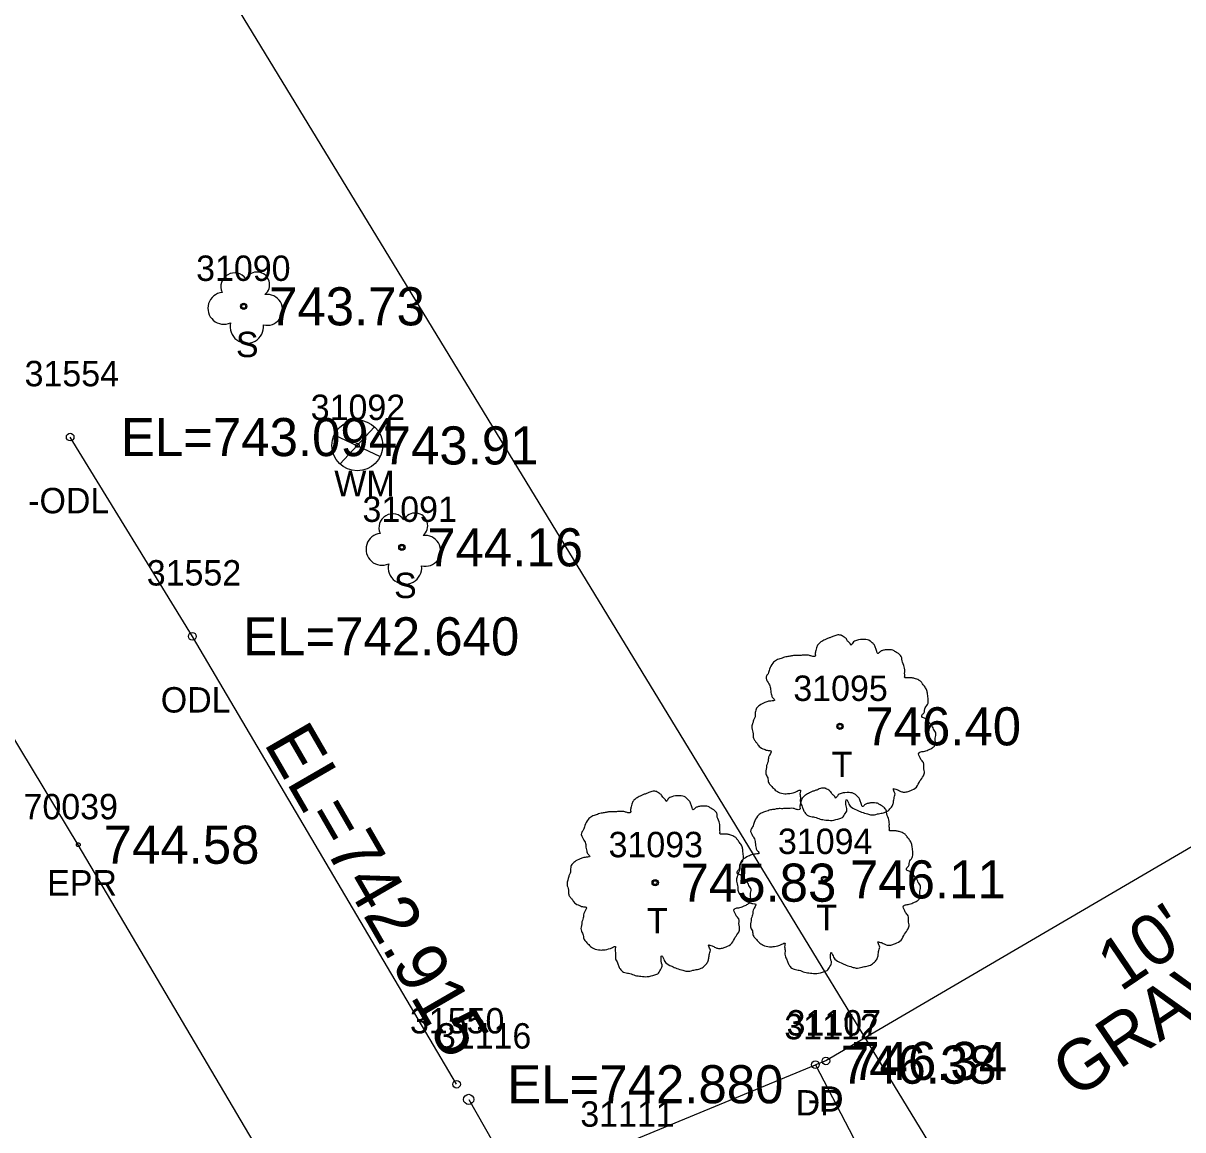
# Model space of a CAD drawing. Extents: x 1375131 to 1378678, y 999028 to 1004053.
# Drawn here: x 1377868.14 to 1377913.81, y 1000838.71 to 1000882.28 of the extents above; entities that cross this region are included whole.
import ezdxf

# ---------------------------------------------------------------- set-up
doc = ezdxf.new("R2010")
doc.units = 0
for name, color, linetype in [('RD_EX_DR_Pipe', 7, 'Continuous'), ('RD_EX_DR_Pipe_txCode', 7, 'Continuous'), ('RD_EX_Driveway', 7, 'Continuous'), ('RD_EX_Driveway_txCode', 7, 'Continuous'), ('RD_EX_H2O', 7, 'Continuous'), ('RD_EX_H2O_txCode', 7, 'Continuous'), ('RD_EX_Road', 7, 'Continuous'), ('RD_EX_Road_txCode', 7, 'Continuous'), ('RD_EX_RW', 7, 'Continuous'), ('RD_EX_TX_Driveway_ELEV', 7, 'Continuous'), ('RD_EX_TX_H2O_ELEV', 7, 'Continuous'), ('RD_EX_TX_Road_ELEV', 7, 'Continuous'), ('RD_EX_TX_UT_ELEV', 7, 'Continuous'), ('RD_EX_TX_VEG_ELEV', 7, 'Continuous'), ('RD_EX_UT', 7, 'Continuous'), ('RD_EX_UT_txCode', 7, 'Continuous'), ('RD_EX_VEG', 7, 'Continuous'), ('RD_EX_VEG_txCode', 7, 'Continuous'), ('RD_SMD_Locator', 7, 'Continuous'), ('RD_TX_Misc2', 7, 'Continuous'), ('RD_TX_Pipe_ElevEX', 7, 'Continuous')]:
    doc.layers.add(name, color=color, linetype=linetype)

msp = doc.modelspace()

# ---------------------------------------------------------------- linework, layer by layer
at = {"layer": 'RD_EX_DR_Pipe'}
msp.add_line((1377885.684, 1000839.91), (1377895.89, 1000822.121), dxfattribs=at)
at = {"layer": 'RD_EX_Driveway'}
for points in [[(1377966.861, 1000881.398), (1377933.173, 1000860.964), (1377899.756, 1000841.424), (1377899.343, 1000841.276)], [(1377878.223, 1000836.536), (1377891.027, 1000837.833), (1377899.343, 1000841.276), (1377903.835, 1000832.654), (1377898.158, 1000826.934), (1377890.381, 1000815.954)]]:
    msp.add_lwpolyline(points, dxfattribs=at)
at = {"layer": 'RD_EX_H2O'}
msp.add_lwpolyline([(1377885.206, 1000840.506), (1377874.8, 1000858.139), (1377869.987, 1000865.983)], dxfattribs=at)
at = {"layer": 'RD_EX_Road'}
msp.add_lwpolyline([(1377899.668, 1000800.294), (1377898.717, 1000801.843), (1377870.308, 1000849.935), (1377847.281, 1000887.888), (1377815.153, 1000940.575), (1377781.512, 1000995.259), (1377748.623, 1001049.208), (1377716.579, 1001099.532), (1377686.671, 1001148.78), (1377656.469, 1001199.107), (1377629.542, 1001244.184), (1377599.886, 1001292.672), (1377570.873, 1001341.428), (1377539.828, 1001392.468), (1377511.01, 1001440.306), (1377480.717, 1001489.998), (1377449.725, 1001541.494), (1377420.899, 1001591.946), (1377390.45, 1001644.414)], dxfattribs=at)
at = {"layer": 'RD_EX_RW'}
msp.add_line((1377592.75, 1001348.439), (1377983.574, 1000707.362), dxfattribs=at)
at = {"layer": 'RD_EX_UT'}
for p, q in [((1377880.622, 1000864.926), (1377881.956, 1000866.374)), ((1377880.381, 1000866.074), (1377882.197, 1000865.217))]:
    msp.add_line(p, q, dxfattribs=at)
msp.add_circle((1377881.298, 1000865.655), 1, dxfattribs=at)
at = {"layer": 'RD_EX_VEG'}
for centre, radius in [((1377876.823, 1000871.131), 0.125), ((1377883.052, 1000861.644), 0.125), ((1377900.307, 1000854.596), 0.125), ((1377900.301, 1000854.587), 0.00005), ((1377893.03, 1000848.442), 0.125), ((1377893.024, 1000848.433), 0.00005), ((1377899.702, 1000848.569), 0.125), ((1377899.696, 1000848.56), 0.00005)]:
    msp.add_circle(centre, radius, dxfattribs=at)
for centre, radius, start, end in [((1377876.462, 1000871.905), 0.542, 34.9763, 204.756), ((1377877.346, 1000871.982), 0.497, 308.7626, 152.0467), ((1377876.041, 1000871.053), 0.628, 96.4518, 294.734), ((1377877.743, 1000870.991), 0.609, 256.5667, 98.1046), ((1377876.946, 1000870.333), 0.659, 166.8827, 5.7589), ((1377882.691, 1000862.418), 0.542, 34.9763, 204.756), ((1377883.575, 1000862.495), 0.497, 308.7626, 152.0467), ((1377882.27, 1000861.566), 0.628, 96.4518, 294.734), ((1377883.972, 1000861.504), 0.609, 256.5667, 98.1046), ((1377883.175, 1000860.846), 0.659, 166.8827, 5.7589)]:
    msp.add_arc(centre, radius, start, end, dxfattribs=at)
for points in [[(1377900.373, 1000858.18), (1377900.223, 1000858.192), (1377900.061, 1000858.142), (1377899.936, 1000858.092), (1377899.823, 1000858.055), (1377899.711, 1000858.005), (1377899.561, 1000857.917), (1377899.448, 1000857.817), (1377899.386, 1000857.692), (1377899.361, 1000857.58), (1377899.336, 1000857.442), (1377899.336, 1000857.355), (1377899.273, 1000857.342), (1377899.198, 1000857.355), (1377899.074, 1000857.392), (1377898.949, 1000857.392), (1377898.824, 1000857.392), (1377898.649, 1000857.38), (1377898.474, 1000857.38), (1377898.336, 1000857.355), (1377898.174, 1000857.33), (1377897.987, 1000857.268), (1377897.812, 1000857.205), (1377897.662, 1000857.08), (1377897.537, 1000856.843), (1377897.474, 1000856.668), (1377897.399, 1000856.543), (1377897.474, 1000856.318), (1377897.562, 1000856.143), (1377897.574, 1000856.043), (1377897.612, 1000855.831), (1377897.662, 1000855.718), (1377897.724, 1000855.618), (1377897.687, 1000855.606), (1377897.499, 1000855.581), (1377897.349, 1000855.531), (1377897.137, 1000855.418), (1377897.024, 1000855.306), (1377896.974, 1000855.143), (1377896.962, 1000854.969), (1377896.912, 1000854.869), (1377896.875, 1000854.731), (1377896.862, 1000854.694), (1377896.837, 1000854.531), (1377896.887, 1000854.306), (1377896.9, 1000854.131), (1377896.962, 1000854.019), (1377897.037, 1000853.932), (1377897.124, 1000853.807), (1377897.324, 1000853.694), (1377897.487, 1000853.644), (1377897.587, 1000853.632), (1377897.499, 1000853.382), (1377897.474, 1000853.207), (1377897.412, 1000853.007), (1377897.412, 1000852.969), (1377897.387, 1000852.732), (1377897.462, 1000852.57), (1377897.499, 1000852.382), (1377897.587, 1000852.27), (1377897.724, 1000852.12), (1377897.887, 1000852.007), (1377898.136, 1000851.945), (1377898.336, 1000851.957), (1377898.624, 1000852.045), (1377898.749, 1000852.082), (1377898.736, 1000851.995), (1377898.749, 1000851.807), (1377898.749, 1000851.595), (1377898.824, 1000851.433), (1377898.874, 1000851.295), (1377898.949, 1000851.17), (1377899.111, 1000851.058), (1377899.311, 1000851.02), (1377899.523, 1000850.945), (1377899.748, 1000850.908), (1377899.998, 1000850.895), (1377900.298, 1000850.97), (1377900.435, 1000851.033), (1377900.485, 1000851.12), (1377900.585, 1000851.308), (1377900.56, 1000851.42), (1377900.573, 1000851.72), (1377900.623, 1000851.632), (1377900.71, 1000851.458), (1377900.96, 1000851.308), (1377901.16, 1000851.22), (1377901.398, 1000851.145), (1377901.547, 1000851.108), (1377901.785, 1000851.145), (1377901.972, 1000851.183), (1377902.16, 1000851.245), (1377902.31, 1000851.383), (1377902.397, 1000851.52), (1377902.422, 1000851.657), (1377902.46, 1000851.845), (1377902.485, 1000851.932)], [(1377902.485, 1000851.932), (1377902.447, 1000852.02), (1377902.422, 1000852.145), (1377902.46, 1000852.132), (1377902.547, 1000852.107), (1377902.684, 1000852.045), (1377902.797, 1000852.007), (1377902.959, 1000852.02), (1377903.097, 1000852.07), (1377903.322, 1000852.207), (1377903.459, 1000852.445), (1377903.597, 1000852.645), (1377903.634, 1000852.807), (1377903.609, 1000852.919), (1377903.597, 1000853.169), (1377903.497, 1000853.294), (1377903.472, 1000853.357), (1377903.422, 1000853.557), (1377903.459, 1000853.582), (1377903.597, 1000853.607), (1377903.784, 1000853.669), (1377903.921, 1000853.732), (1377904.034, 1000853.819), (1377904.071, 1000853.932), (1377904.059, 1000854.131), (1377904.084, 1000854.331), (1377904.046, 1000854.406), (1377903.996, 1000854.481), (1377903.959, 1000854.581), (1377903.884, 1000854.656), (1377903.834, 1000854.731), (1377903.784, 1000854.781), (1377903.722, 1000854.856), (1377903.634, 1000854.919), (1377903.559, 1000854.944), (1377903.534, 1000855.019), (1377903.609, 1000855.118), (1377903.634, 1000855.168), (1377903.647, 1000855.281), (1377903.759, 1000855.456), (1377903.784, 1000855.656), (1377903.759, 1000855.868), (1377903.734, 1000856.006), (1377903.659, 1000856.143), (1377903.559, 1000856.268), (1377903.497, 1000856.355), (1377903.409, 1000856.418), (1377903.247, 1000856.48), (1377903.122, 1000856.505), (1377902.947, 1000856.505), (1377902.847, 1000856.53), (1377902.859, 1000856.555), (1377902.859, 1000856.63), (1377902.859, 1000856.768), (1377902.822, 1000856.993), (1377902.747, 1000857.243), (1377902.747, 1000857.255), (1377902.697, 1000857.38), (1377902.585, 1000857.48), (1377902.497, 1000857.53), (1377902.397, 1000857.592), (1377902.272, 1000857.605), (1377902.122, 1000857.605), (1377901.985, 1000857.58), (1377901.885, 1000857.53), (1377901.797, 1000857.467), (1377901.76, 1000857.542), (1377901.71, 1000857.692), (1377901.685, 1000857.767), (1377901.61, 1000857.855), (1377901.498, 1000857.955), (1377901.273, 1000858.017), (1377900.96, 1000857.98), (1377900.81, 1000857.88), (1377900.735, 1000857.792), (1377900.71, 1000857.855), (1377900.61, 1000857.955), (1377900.56, 1000858.042), (1377900.473, 1000858.105), (1377900.398, 1000858.155), (1377900.348, 1000858.18)], [(1377893.096, 1000852.026), (1377892.946, 1000852.038), (1377892.784, 1000851.988), (1377892.659, 1000851.938), (1377892.546, 1000851.901), (1377892.434, 1000851.851), (1377892.284, 1000851.763), (1377892.171, 1000851.663), (1377892.109, 1000851.538), (1377892.084, 1000851.426), (1377892.059, 1000851.288), (1377892.059, 1000851.201), (1377891.996, 1000851.188), (1377891.921, 1000851.201), (1377891.797, 1000851.238), (1377891.672, 1000851.238), (1377891.547, 1000851.238), (1377891.372, 1000851.226), (1377891.197, 1000851.226), (1377891.059, 1000851.201), (1377890.897, 1000851.176), (1377890.71, 1000851.114), (1377890.535, 1000851.051), (1377890.385, 1000850.926), (1377890.26, 1000850.689), (1377890.197, 1000850.514), (1377890.122, 1000850.389), (1377890.197, 1000850.164), (1377890.285, 1000849.989), (1377890.297, 1000849.889), (1377890.335, 1000849.677), (1377890.385, 1000849.564), (1377890.447, 1000849.464), (1377890.41, 1000849.452), (1377890.222, 1000849.427), (1377890.072, 1000849.377), (1377889.86, 1000849.264), (1377889.747, 1000849.152), (1377889.697, 1000848.989), (1377889.685, 1000848.815), (1377889.635, 1000848.715), (1377889.598, 1000848.577), (1377889.585, 1000848.54), (1377889.56, 1000848.377), (1377889.61, 1000848.152), (1377889.623, 1000847.977), (1377889.685, 1000847.865), (1377889.76, 1000847.778), (1377889.847, 1000847.653), (1377890.047, 1000847.54), (1377890.21, 1000847.49), (1377890.31, 1000847.478), (1377890.222, 1000847.228), (1377890.197, 1000847.053), (1377890.135, 1000846.853), (1377890.135, 1000846.815), (1377890.11, 1000846.578), (1377890.185, 1000846.416), (1377890.222, 1000846.228), (1377890.31, 1000846.116), (1377890.447, 1000845.966), (1377890.61, 1000845.853), (1377890.859, 1000845.791), (1377891.059, 1000845.803), (1377891.347, 1000845.891), (1377891.472, 1000845.928), (1377891.459, 1000845.841), (1377891.472, 1000845.653), (1377891.472, 1000845.441), (1377891.547, 1000845.279), (1377891.597, 1000845.141), (1377891.672, 1000845.016), (1377891.834, 1000844.904), (1377892.034, 1000844.866), (1377892.246, 1000844.791), (1377892.471, 1000844.754), (1377892.721, 1000844.741), (1377893.021, 1000844.816), (1377893.158, 1000844.879), (1377893.208, 1000844.966), (1377893.308, 1000845.154), (1377893.283, 1000845.266), (1377893.296, 1000845.566), (1377893.346, 1000845.478), (1377893.433, 1000845.304), (1377893.683, 1000845.154), (1377893.883, 1000845.066), (1377894.121, 1000844.991), (1377894.27, 1000844.954), (1377894.508, 1000844.991), (1377894.695, 1000845.029), (1377894.883, 1000845.091), (1377895.033, 1000845.229), (1377895.12, 1000845.366), (1377895.145, 1000845.503), (1377895.183, 1000845.691), (1377895.208, 1000845.778)], [(1377895.208, 1000845.778), (1377895.17, 1000845.866), (1377895.145, 1000845.991), (1377895.183, 1000845.978), (1377895.27, 1000845.953), (1377895.407, 1000845.891), (1377895.52, 1000845.853), (1377895.682, 1000845.866), (1377895.82, 1000845.916), (1377896.045, 1000846.053), (1377896.182, 1000846.291), (1377896.32, 1000846.491), (1377896.357, 1000846.653), (1377896.332, 1000846.765), (1377896.32, 1000847.015), (1377896.22, 1000847.14), (1377896.195, 1000847.203), (1377896.145, 1000847.403), (1377896.182, 1000847.428), (1377896.32, 1000847.453), (1377896.507, 1000847.515), (1377896.644, 1000847.578), (1377896.757, 1000847.665), (1377896.794, 1000847.778), (1377896.782, 1000847.977), (1377896.807, 1000848.177), (1377896.769, 1000848.252), (1377896.719, 1000848.327), (1377896.682, 1000848.427), (1377896.607, 1000848.502), (1377896.557, 1000848.577), (1377896.507, 1000848.627), (1377896.445, 1000848.702), (1377896.357, 1000848.765), (1377896.282, 1000848.79), (1377896.257, 1000848.865), (1377896.332, 1000848.964), (1377896.357, 1000849.014), (1377896.37, 1000849.127), (1377896.482, 1000849.302), (1377896.507, 1000849.502), (1377896.482, 1000849.714), (1377896.457, 1000849.852), (1377896.382, 1000849.989), (1377896.282, 1000850.114), (1377896.22, 1000850.201), (1377896.132, 1000850.264), (1377895.97, 1000850.326), (1377895.845, 1000850.351), (1377895.67, 1000850.351), (1377895.57, 1000850.376), (1377895.582, 1000850.401), (1377895.582, 1000850.476), (1377895.582, 1000850.614), (1377895.545, 1000850.839), (1377895.47, 1000851.089), (1377895.47, 1000851.101), (1377895.42, 1000851.226), (1377895.308, 1000851.326), (1377895.22, 1000851.376), (1377895.12, 1000851.438), (1377894.995, 1000851.451), (1377894.845, 1000851.451), (1377894.708, 1000851.426), (1377894.608, 1000851.376), (1377894.52, 1000851.313), (1377894.483, 1000851.388), (1377894.433, 1000851.538), (1377894.408, 1000851.613), (1377894.333, 1000851.701), (1377894.221, 1000851.801), (1377893.996, 1000851.863), (1377893.683, 1000851.826), (1377893.533, 1000851.726), (1377893.458, 1000851.638), (1377893.433, 1000851.701), (1377893.333, 1000851.801), (1377893.283, 1000851.888), (1377893.196, 1000851.951), (1377893.121, 1000852.001), (1377893.071, 1000852.026)], [(1377899.768, 1000852.153), (1377899.618, 1000852.165), (1377899.456, 1000852.115), (1377899.331, 1000852.065), (1377899.218, 1000852.028), (1377899.106, 1000851.978), (1377898.956, 1000851.89), (1377898.843, 1000851.79), (1377898.781, 1000851.665), (1377898.756, 1000851.553), (1377898.731, 1000851.415), (1377898.731, 1000851.328), (1377898.668, 1000851.315), (1377898.593, 1000851.328), (1377898.469, 1000851.365), (1377898.344, 1000851.365), (1377898.219, 1000851.365), (1377898.044, 1000851.353), (1377897.869, 1000851.353), (1377897.731, 1000851.328), (1377897.569, 1000851.303), (1377897.382, 1000851.241), (1377897.207, 1000851.178), (1377897.057, 1000851.053), (1377896.932, 1000850.816), (1377896.869, 1000850.641), (1377896.794, 1000850.516), (1377896.869, 1000850.291), (1377896.957, 1000850.116), (1377896.969, 1000850.016), (1377897.007, 1000849.804), (1377897.057, 1000849.691), (1377897.119, 1000849.591), (1377897.082, 1000849.579), (1377896.894, 1000849.554), (1377896.744, 1000849.504), (1377896.532, 1000849.391), (1377896.419, 1000849.279), (1377896.369, 1000849.116), (1377896.357, 1000848.942), (1377896.307, 1000848.842), (1377896.27, 1000848.704), (1377896.257, 1000848.667), (1377896.232, 1000848.504), (1377896.282, 1000848.279), (1377896.295, 1000848.104), (1377896.357, 1000847.992), (1377896.432, 1000847.905), (1377896.519, 1000847.78), (1377896.719, 1000847.667), (1377896.882, 1000847.617), (1377896.982, 1000847.605), (1377896.894, 1000847.355), (1377896.869, 1000847.18), (1377896.807, 1000846.98), (1377896.807, 1000846.942), (1377896.782, 1000846.705), (1377896.857, 1000846.543), (1377896.894, 1000846.355), (1377896.982, 1000846.243), (1377897.119, 1000846.093), (1377897.282, 1000845.98), (1377897.531, 1000845.918), (1377897.731, 1000845.93), (1377898.019, 1000846.018), (1377898.144, 1000846.055), (1377898.131, 1000845.968), (1377898.144, 1000845.78), (1377898.144, 1000845.568), (1377898.219, 1000845.406), (1377898.269, 1000845.268), (1377898.344, 1000845.143), (1377898.506, 1000845.031), (1377898.706, 1000844.993), (1377898.918, 1000844.918), (1377899.143, 1000844.881), (1377899.393, 1000844.868), (1377899.693, 1000844.943), (1377899.83, 1000845.006), (1377899.88, 1000845.093), (1377899.98, 1000845.281), (1377899.955, 1000845.393), (1377899.968, 1000845.693), (1377900.018, 1000845.605), (1377900.105, 1000845.431), (1377900.355, 1000845.281), (1377900.555, 1000845.193), (1377900.793, 1000845.118), (1377900.942, 1000845.081), (1377901.18, 1000845.118), (1377901.367, 1000845.156), (1377901.555, 1000845.218), (1377901.705, 1000845.356), (1377901.792, 1000845.493), (1377901.817, 1000845.63), (1377901.855, 1000845.818), (1377901.88, 1000845.905)], [(1377901.88, 1000845.905), (1377901.842, 1000845.993), (1377901.817, 1000846.118), (1377901.855, 1000846.105), (1377901.942, 1000846.08), (1377902.079, 1000846.018), (1377902.192, 1000845.98), (1377902.354, 1000845.993), (1377902.492, 1000846.043), (1377902.717, 1000846.18), (1377902.854, 1000846.418), (1377902.992, 1000846.618), (1377903.029, 1000846.78), (1377903.004, 1000846.892), (1377902.992, 1000847.142), (1377902.892, 1000847.267), (1377902.867, 1000847.33), (1377902.817, 1000847.53), (1377902.854, 1000847.555), (1377902.992, 1000847.58), (1377903.179, 1000847.642), (1377903.316, 1000847.705), (1377903.429, 1000847.792), (1377903.466, 1000847.905), (1377903.454, 1000848.104), (1377903.479, 1000848.304), (1377903.441, 1000848.379), (1377903.391, 1000848.454), (1377903.354, 1000848.554), (1377903.279, 1000848.629), (1377903.229, 1000848.704), (1377903.179, 1000848.754), (1377903.117, 1000848.829), (1377903.029, 1000848.892), (1377902.954, 1000848.917), (1377902.929, 1000848.992), (1377903.004, 1000849.091), (1377903.029, 1000849.141), (1377903.042, 1000849.254), (1377903.154, 1000849.429), (1377903.179, 1000849.629), (1377903.154, 1000849.841), (1377903.129, 1000849.979), (1377903.054, 1000850.116), (1377902.954, 1000850.241), (1377902.892, 1000850.328), (1377902.804, 1000850.391), (1377902.642, 1000850.453), (1377902.517, 1000850.478), (1377902.342, 1000850.478), (1377902.242, 1000850.503), (1377902.254, 1000850.528), (1377902.254, 1000850.603), (1377902.254, 1000850.741), (1377902.217, 1000850.966), (1377902.142, 1000851.216), (1377902.142, 1000851.228), (1377902.092, 1000851.353), (1377901.98, 1000851.453), (1377901.892, 1000851.503), (1377901.792, 1000851.565), (1377901.667, 1000851.578), (1377901.517, 1000851.578), (1377901.38, 1000851.553), (1377901.28, 1000851.503), (1377901.192, 1000851.44), (1377901.155, 1000851.515), (1377901.105, 1000851.665), (1377901.08, 1000851.74), (1377901.005, 1000851.828), (1377900.893, 1000851.928), (1377900.668, 1000851.99), (1377900.355, 1000851.953), (1377900.205, 1000851.853), (1377900.13, 1000851.765), (1377900.105, 1000851.828), (1377900.005, 1000851.928), (1377899.955, 1000852.015), (1377899.868, 1000852.078), (1377899.793, 1000852.128), (1377899.743, 1000852.153)]]:
    msp.add_spline(points, degree=3, dxfattribs=at)
at = {"layer": 'RD_SMD_Locator'}
for centre, radius in [((1377876.823, 1000871.131), 0.075), ((1377869.987, 1000865.983), 0.15), ((1377881.298, 1000865.655), 0.075), ((1377883.052, 1000861.644), 0.075), ((1377874.8, 1000858.139), 0.15), ((1377900.307, 1000854.596), 0.075), ((1377870.308, 1000849.935), 0.075), ((1377893.03, 1000848.442), 0.075), ((1377899.702, 1000848.569), 0.075), ((1377899.756, 1000841.424), 0.15), ((1377899.343, 1000841.276), 0.15), ((1377885.206, 1000840.506), 0.15), ((1377885.684, 1000839.91), 0.2)]:
    msp.add_circle(centre, radius, dxfattribs=at)

# ---------------------------------------------------------------- texts
at = {"layer": 'RD_EX_DR_Pipe_txCode'}
msp.add_text('31116', height=1, dxfattribs=at).set_placement((1377884.432, 1000841.91))
at = {"layer": 'RD_EX_Driveway_txCode'}
for s, p in [('31112', (1377898.115, 1000842.276)), ('31107', (1377898.205, 1000842.424)), ('DP', (1377898.563, 1000839.276)), ('-D', (1377899.039, 1000839.424)), ('31111', (1377890.082, 1000838.833))]:
    msp.add_text(s, height=1, dxfattribs=at).set_placement(p)
at = {"layer": 'RD_EX_H2O_txCode'}
for s, p in [('31554', (1377868.192, 1000867.983)), ('-ODL', (1377868.333, 1000862.983)), ('31552', (1377873.005, 1000860.139)), ('ODL', (1377873.556, 1000855.139)), ('31550', (1377883.371, 1000842.506))]:
    msp.add_text(s, height=1, dxfattribs=at).set_placement(p)
at = {"layer": 'RD_EX_Road_txCode'}
for s, p in [('70039', (1377868.151, 1000850.935)), ('EPR', (1377869.08, 1000847.935))]:
    msp.add_text(s, height=1, dxfattribs=at).set_placement(p)
at = {"layer": 'RD_EX_TX_Driveway_ELEV'}
for s, p in [('746.38', (1377900.343, 1000840.526)), ('746.34', (1377900.756, 1000840.674))]:
    msp.add_text(s, height=1.5, dxfattribs=at).set_placement(p)
at = {"layer": 'RD_EX_TX_H2O_ELEV'}
for s, p in [('EL=743.094', (1377871.987, 1000865.233)), ('EL=742.640', (1377876.8, 1000857.389)), ('EL=742.880', (1377887.206, 1000839.756))]:
    msp.add_text(s, height=1.5, dxfattribs=at).set_placement(p)
at = {"layer": 'RD_EX_TX_Road_ELEV'}
msp.add_text('744.58', height=1.5, dxfattribs=at).set_placement((1377871.308, 1000849.185))
at = {"layer": 'RD_EX_TX_UT_ELEV'}
msp.add_text('743.91', height=1.5, dxfattribs=at).set_placement((1377882.298, 1000864.905))
at = {"layer": 'RD_EX_TX_VEG_ELEV'}
for s, p in [('743.73', (1377877.823, 1000870.381)), ('744.16', (1377884.052, 1000860.894)), ('746.40', (1377901.307, 1000853.846)), ('745.83', (1377894.03, 1000847.692)), ('746.11', (1377900.702, 1000847.819))]:
    msp.add_text(s, height=1.5, dxfattribs=at).set_placement(p)
at = {"layer": 'RD_EX_UT_txCode'}
for s, p in [('31092', (1377879.463, 1000866.655)), ('WM', (1377880.392, 1000863.655))]:
    msp.add_text(s, height=1, dxfattribs=at).set_placement(p)
at = {"layer": 'RD_EX_VEG_txCode'}
for s, p in [('31090', (1377874.949, 1000872.131)), ('S', (1377876.516, 1000869.131)), ('31091', (1377881.501, 1000862.644)), ('S', (1377882.745, 1000859.644)), ('31095', (1377898.472, 1000855.596)), ('T', (1377899.984, 1000852.596)), ('31094', (1377897.867, 1000849.569)), ('31093', (1377891.195, 1000849.442)), ('T', (1377892.707, 1000846.442)), ('T', (1377899.379, 1000846.569))]:
    msp.add_text(s, height=1, dxfattribs=at).set_placement(p)
at = {"layer": 'RD_TX_Misc2'}
for s, p in [("10'", (1377911.353, 1000844.119)), ('GRAVEL', (1377909.573, 1000839.895))]:
    msp.add_text(s, height=2, rotation=34.0993, dxfattribs=at).set_placement(p)
at = {"layer": 'RD_TX_Pipe_ElevEX'}
msp.add_text('EL=742.915', height=2, rotation=300.057, dxfattribs=at).set_placement((1377877.589, 1000853.936))

doc.saveas('drawing.dxf')
